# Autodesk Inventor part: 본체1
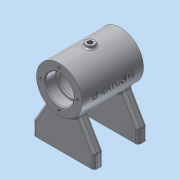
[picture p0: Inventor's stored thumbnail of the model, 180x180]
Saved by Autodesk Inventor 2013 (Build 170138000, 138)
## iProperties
Created: 2018-05
Part Number: 본체1
Material: 알루미늄 6061
Document SubType Name: Modeling
Designer: dgall
Density: 2.71 g/cm^3
Mass: 319.125 g
Surface Area: 378.357 cm^2
Volume: 117.758 cm^3
Author: dgall
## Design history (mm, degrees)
sketch "스케치1"
  geometry: L1 (-35, 16)-(-35, 26); L2 (-35, 26)-(35, 26); L3 (35, 26)-(35, 16); L4 (35, 16)-(23.3, 16); L5 (23, 15.7)-(23, 14); L6 (23, 14)-(21, 14); L7 (21, 14)-(21, 18); L8 (18, 21)-(-18, 21); L9 (-21, 18)-(-21, 14); L10 (-21, 14)-(-23, 14); L11 (-23, 14)-(-23, 15.7); L12 (-23.3, 16)-(-35, 16); L13 (-37.023, 0)-(37.902, 0); A1 r 3 centre (-18, 18) between (-18, 21) and (-21, 18); A2 r 3 centre (18, 18) between (21, 18) and (18, 21); A3 r 0.3 centre (-23.3, 15.7) between (-23, 15.7) and (-23.3, 16); A4 r 0.3 centre (23.3, 15.7) between (23.3, 16) and (23, 15.7); 5 further points
  constraints: 26 end point, 9 parallel, 9 point on line, 8 point on circle, 8 tangent, 4 centre point, 3 perpendicular, 2 equal radius, 1 vertical
  dimensions: "d0" = 70 distance between parallel lines of L3 L1; "d2" = 35 distance from line of point (0, 0) L1; "d3" = 52 diameter of L2 L13; "d4" = 42 diameter of L8 L13; "d5" = 42 distance of point (21, 21) point (-21, 21); "d6" = 28 diameter of L10 L13; "d7" = 32 diameter of L12 L13; "d8" = 12 distance of point (-23, 16) L1.start; "d9" = 12 distance of L3.end point (23, 16); "d10" = 2 distance of L5.end L6.end; "d11" = 32 diameter of L4 L13; "d12" = 28 diameter of L6 L13; "d13" = 3 radius of A1; "d99" = 0.3 radius of A3
revolve "회전1" sketch "스케치1" stored, may be unused: angle "d14" = 90 deg
node "작업 평면1"
node "작업 평면2"
node "작업 평면4"
  node "작업 평면3"
sketch "스케치4"
  geometry: C1 r 5 at (0, 0); 1 further point
  constraints: 1 centre point, 1 coincident
  dimensions: "d40" = 10 diameter of C1
extrude "돌출3" join sketch "스케치4" stored distance "d42" = 10; taper "d43" = 0 deg
sketch "스케치5"
  geometry: C1 r 5 at (0, 0) reference; C2 r 3 at (0, 0)
  constraints: 1 centre point, 1 coincident
  dimensions: "d44" = 6 diameter of C2
hole "구멍1" sketch "스케치5" at (0, 0) diameter "d46" = 5.188; stored, may be unused: countersink angle "d50" = 90 deg, drill point angle "d52" = 118 deg; dims "d47" = 6, "d48" = 4, "d49" = 2, "d51" = 8
fillet "모깎기1" dims "d53" = 2
sketch "스케치7" dims "d69" = 42
  geometry: L1 (0, 0)-(-21, 0); C1 r 16 at (0, 0) reference; C2 r 26 at (0, 0) reference; C3 r 2 at (-21, 0); C4 r 2 at (0, -21); C5 r 2 at (21, 0); C6 r 2 at (0, 21)
  constraints: 4 centre point, 2 coincident, 2 end point, 1 horizontal, 1 horizontal alignment, 11 other
  dimensions: "d71" = 4 diameter of C3; "d74" = 360 deg dimension on C1.centre C3.centre (derived)
hole "구멍3" sketch "스케치7" at (-21, 0), (0, 21), (21, 0), (0, -21) diameter "d76" = 3.242; stored, may be unused: countersink angle "d80" = 90 deg, drill point angle "d82" = 118 deg; dims "d77" = 8, "d78" = 4, "d79" = 2, "d81" = 10
node "작업 평면6"
  node "작업 평면5"
sketch "스케치9"
  geometry: C1 r 6 at (0, 0); 1 further point
  constraints: 1 centre point, 1 coincident
  dimensions: "d85" = 12 diameter of C1
extrude "돌출4" join sketch "스케치9" stored distance "d87" = 10; taper "d88" = 0 deg
sketch "스케치10"
  geometry: C1 r 6 at (0, 0) reference; C2 r 3 at (0, 0)
  constraints: 1 centre point, 1 coincident
  dimensions: "d89" = 6 diameter of C2
hole "구멍4" sketch "스케치10" at (0, 0) diameter "d91" = 5.242; stored, may be unused: countersink angle "d95" = 90 deg, drill point angle "d97" = 118 deg; dims "d92" = 8, "d93" = 4, "d94" = 2, "d96" = 10
fillet "모깎기4" dims "d98" = 2
node "작업 평면8"
sketch "스케치12"
  geometry: L1 (-35, -65)-(35, -65); L2 (-35, -65)-(-35, -50); L3 (35, -65)-(35, -50); L4 (-35, -50)-(-17.325, -19.386); L5 (35, -50)-(17.325, -19.386); A1 r 26 centre (0, 0) between (-17.325, -19.386) and (17.325, -19.386) reference; 1 further point
  constraints: 10 end point, 2 point on circle, 1 horizontal, 1 parallel, 1 perpendicular
  dimensions: "d105" = 70 distance of L1.start L1.end; "d107" = 35 horizontal distance of L1.start point (0, 0); "d108" = 65 distance from line of L1 point (0, 0); "d109" = 15 distance of L1.start L2.end; "d110" = 15 distance of L1.end L3.end; "d111" = 30 deg angle of L4 L2; "d112" = 30 deg angle of L5 L3
extrude "돌출6" join sketch "스케치12" distance "d113" = 10; taper "d114" = 0 deg
sketch "스케치13"
  geometry: L1 (0, 70)-(0, 0) reference; C1 r 2.5 at (5, 55); C2 r 2.5 at (5, 15); 1 further point
  constraints: 2 centre point
  dimensions: "d115" = 5 diameter of C1; "d117" = 5 diameter of C2; "d118" = 5 distance from line of L1 C1.centre; "d119" = 5 distance from line of L1 C2.centre; "d120" = 20 vertical distance of point (-20, 35) C1.centre; "d121" = 20 vertical distance of point (-20, 35) C2.centre
hole "구멍5" sketch "스케치13" at (5, 15), (5, 55) diameter "d122" = 4.134; stored, may be unused: countersink angle "d126" = 90 deg, drill point angle "d128" = 118 deg; dims "d123" = 8, "d124" = 4, "d125" = 2, "d127" = 10
fillet "모깎기5" dims "d129" = 3
fillet "모깎기6" dims "d130" = 3
node "작업 평면9"
sketch "스케치15"
  geometry: L1 (-24.887, 3.602)-(24.887, 3.602); L2 (24.887, 3.602)-(24.887, -3.602); L3 (24.887, -3.602)-(-24.887, -3.602); L4 (-24.887, -3.602)-(-24.887, 3.602); L5 (-24.887, 0)-(24.887, 0); L6 (0, 3.602)-(0, -3.602); L7 (-35, -26)-(-35, 26) reference; L8 (-35, 26)-(35, 26) reference; 1 further point
  constraints: 4 end point, 4 midpoint, 2 other
  dimensions: "d131" = 35 distance between parallel lines of L7 L6; "d132" = 26 distance between parallel lines of L8 L5
extrude "돌출7" join sketch "스케치15" distance "d133" = 0.5; taper "d134" = 0 deg
chamfer "모따기1" distance "d135" = 1; stored, may be unused: second distance "d136" = 2, angle "d137" = 45 deg
chamfer "모따기2" distance "d138" = 1; stored, may be unused: second distance "d139" = 2, angle "d140" = 45 deg
node "솔리드1"
mirror "대칭2"
mirror "대칭3"
mirror "대칭4"
other parameters: "d39" = 3, "d83" = 20 deg, "d84" = -29
